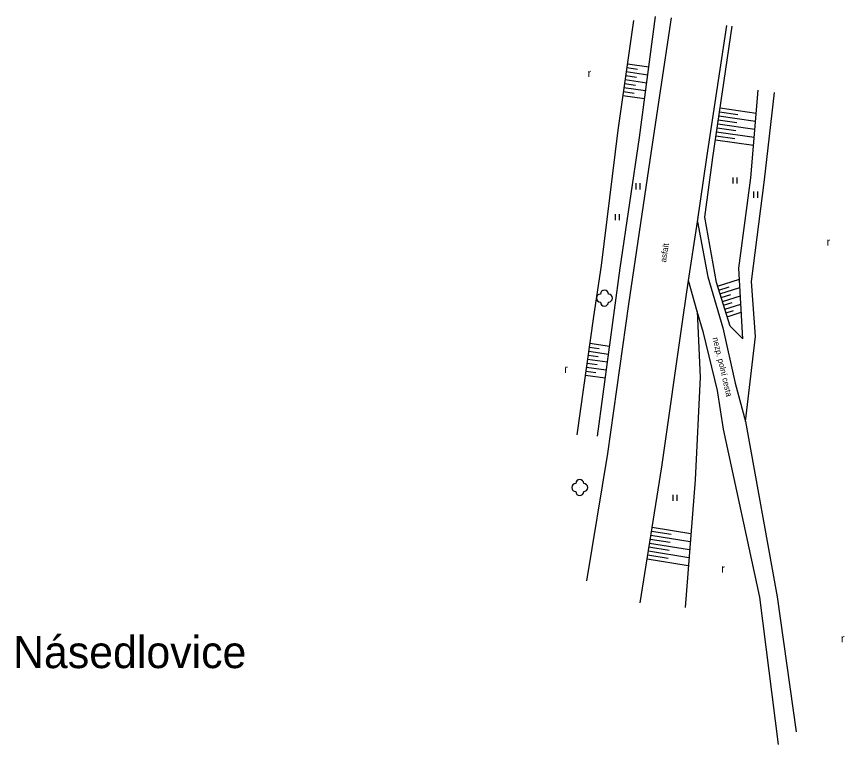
# Model space of a CAD drawing. Extents: x -582162 to -561283, y -1187583 to -1183539.
# Drawn here: x -575105.1 to -575001.7, y -1184397 to -1184306.2 of the extents above; entities that cross this region are included whole.
import ezdxf

# ---------------------------------------------------------------- set-up
doc = ezdxf.new("R2010")
doc.units = 0
for name, color, linetype in [('Vrstva 1', 7, 'Continuous'), ('Vrstva 10', 7, 'Continuous'), ('Vrstva 11', 7, 'Continuous'), ('Vrstva 12', 7, 'Continuous'), ('Vrstva 14', 7, 'Continuous'), ('Vrstva 17', 7, 'Continuous'), ('Vrstva 3', 7, 'Continuous')]:
    doc.layers.add(name, color=color, linetype=linetype)

# ---------------------------------------------------------------- blocks, each defined once
blk = doc.blocks.new('3.130')
at = {"layer": 'Vrstva 1'}
blk.add_circle((0, 0), 0.001, dxfattribs=at)
for centre, start, end in [((-1, 0), 90, 270), ((0, 1), 0, 180), ((1, 0), 270, 90), ((0, -1), 180, 360)]:
    blk.add_arc(centre, 1, start, end, dxfattribs=at)
blk = doc.blocks.new('3.019')
at = {"layer": 'Vrstva 1'}
blk.add_text('r', height=2, dxfattribs=at).set_placement((-0.496, -0.964))
blk = doc.blocks.new('3.060')
at = {"layer": 'Vrstva 1'}
for p, q in [((-0.5, -0.75), (-0.5, 0.75)), ((0.5, -0.75), (0.5, 0.75))]:
    blk.add_line(p, q, dxfattribs=at)

msp = doc.modelspace()

# ---------------------------------------------------------------- linework, layer by layer
at = {"layer": 'Vrstva 10'}
for points in [[(-575023.38, -1184306.34), (-575025.69, -1184321.89), (-575028.68, -1184342.1), (-575031.34, -1184360.73), (-575033.94, -1184376.61)], [(-575020.08, -1184331.81), (-575018.9, -1184323.77), (-575016.4, -1184307.33)], [(-575021.19, -1184339.11), (-575020.08, -1184331.81)], [(-575020.08, -1184331.81), (-575018.8, -1184338.69), (-575016.92, -1184345.02), (-575015.4, -1184351.95), (-575014.07, -1184356.71), (-575010.14, -1184378.61), (-575007.78, -1184395.44)], [(-575027.26, -1184379.33), (-575024.53, -1184362.37), (-575021.86, -1184343.7), (-575021.19, -1184339.11)], [(-575020.14, -1184342.98), (-575021.19, -1184339.11)], [(-575009.98, -1184397.01), (-575012.31, -1184378.63), (-575016.85, -1184357.66), (-575017.6, -1184352.85), (-575019.32, -1184345.64), (-575020.14, -1184342.98)]]:
    msp.add_lwpolyline(points, dxfattribs=at)
at = {"layer": 'Vrstva 11'}
msp.add_lwpolyline([(-575014.07, -1184356.71), (-575012.85, -1184346.12), (-575013.35, -1184339.27), (-575011.73, -1184326.56), (-575010.46, -1184315.68)], dxfattribs=at)
at = {"layer": 'Vrstva 12'}
for points in [[(-575028.06, -1184306.68), (-575030.03, -1184320.36), (-575032.1, -1184337.26), (-575033.05, -1184343.61), (-575035.13, -1184358.39)], [(-575032.59, -1184358.55), (-575029.74, -1184337.6), (-575027.34, -1184321.29), (-575025.33, -1184306.2)], [(-575014.44, -1184346.39), (-575016, -1184344.83), (-575017.73, -1184339.37), (-575019.16, -1184331.23), (-575018.18, -1184323.79), (-575015.77, -1184307.41)], [(-575028.84, -1184312.08), (-575026.16, -1184312.46)], [(-575028.98, -1184313.07), (-575026.3, -1184313.45)], [(-575028.91, -1184312.57), (-575027.57, -1184312.76)], [(-575029.12, -1184314.06), (-575026.43, -1184314.45)], [(-575029.05, -1184313.56), (-575027.71, -1184313.76)], [(-575029.27, -1184315.05), (-575026.56, -1184315.44)], [(-575029.19, -1184314.55), (-575027.84, -1184314.75)], [(-575029.41, -1184316.04), (-575026.69, -1184316.43)], [(-575029.34, -1184315.54), (-575027.98, -1184315.74)], [(-575014.44, -1184346.39), (-575014.91, -1184337.61), (-575013.42, -1184326.31), (-575012.5, -1184315.4)], [(-575017.34, -1184318.09), (-575015.06, -1184318.43)], [(-575017.27, -1184317.6), (-575012.74, -1184318.27)], [(-575017.49, -1184319.08), (-575015.18, -1184319.42)], [(-575017.42, -1184318.59), (-575012.83, -1184319.26)], [(-575017.63, -1184320.07), (-575015.29, -1184320.42)], [(-575017.56, -1184319.58), (-575012.91, -1184320.26)], [(-575017.85, -1184321.56), (-575013.08, -1184322.26)], [(-575017.78, -1184321.06), (-575015.41, -1184321.41)], [(-575017.71, -1184320.57), (-575012.99, -1184321.26)], [(-575017.58, -1184339.84), (-575014.84, -1184338.97)], [(-575017.43, -1184340.32), (-575016.12, -1184339.9)], [(-575017.28, -1184340.79), (-575014.78, -1184340)], [(-575017.13, -1184341.27), (-575015.94, -1184340.89)], [(-575016.98, -1184341.75), (-575014.73, -1184341.03)], [(-575016.83, -1184342.22), (-575015.76, -1184341.89)], [(-575016.68, -1184342.7), (-575014.67, -1184342.07)], [(-575020.14, -1184342.98), (-575019.76, -1184351.19), (-575020.38, -1184364), (-575021.64, -1184379.92)], [(-575016.52, -1184343.18), (-575015.58, -1184342.88)], [(-575016.37, -1184343.65), (-575014.62, -1184343.1)], [(-575033.52, -1184346.96), (-575031.06, -1184347.31)], [(-575033.73, -1184348.45), (-575032.5, -1184348.62)], [(-575033.66, -1184347.95), (-575031.19, -1184348.3)], [(-575033.59, -1184347.46), (-575032.36, -1184347.63)], [(-575033.87, -1184349.44), (-575032.63, -1184349.61)], [(-575033.8, -1184348.94), (-575031.33, -1184349.29)], [(-575034.01, -1184350.43), (-575032.77, -1184350.6)], [(-575033.94, -1184349.93), (-575031.47, -1184350.28)], [(-575034.08, -1184350.92), (-575031.6, -1184351.27)], [(-575025.74, -1184369.9), (-575020.91, -1184370.68)], [(-575025.9, -1184370.89), (-575020.99, -1184371.68)], [(-575025.82, -1184370.4), (-575023.39, -1184370.79)], [(-575026.06, -1184371.88), (-575021.07, -1184372.68)], [(-575025.98, -1184371.39), (-575023.5, -1184371.78)], [(-575026.22, -1184372.87), (-575021.15, -1184373.68)], [(-575026.14, -1184372.37), (-575023.62, -1184372.78)], [(-575026.38, -1184373.85), (-575021.23, -1184374.68)], [(-575026.3, -1184373.36), (-575023.74, -1184373.77)]]:
    msp.add_lwpolyline(points, dxfattribs=at)

# ---------------------------------------------------------------- block references
at = {"layer": 'Vrstva 11', "xscale": 0.5, "yscale": 0.5}
for p in [(-575031.7, -1184341.33), (-575034.79, -1184364.96)]:
    msp.add_blockref('3.130', p, dxfattribs=at)
at = {"layer": 'Vrstva 3', "xscale": 0.5, "yscale": 0.5}
for name, p in [('3.019', (-575033.54, -1184313.26)), ('3.060', (-575015.36, -1184326.66)), ('3.060', (-575027.48, -1184327.38)), ('3.060', (-575012.79, -1184328.42)), ('3.060', (-575030.07, -1184331.23)), ('3.019', (-575003.71, -1184334.32)), ('3.019', (-575036.48, -1184350.17)), ('3.060', (-575022.87, -1184366.26)), ('3.019', (-575016.87, -1184375.09)), ('3.019', (-575001.91, -1184383.79))]:
    msp.add_blockref(name, p, dxfattribs=at)

# ---------------------------------------------------------------- texts
at = {"layer": 'Vrstva 14'}
for s, rotation, p in [('asfalt', 81.354, (-575024.01, -1184336.91)), ('nezp. polní cesta', 283.418, (-575018.21, -1184346.31))]:
    msp.add_text(s, height=0.75, rotation=rotation, dxfattribs=at).set_placement(p)
at = {"layer": 'Vrstva 17'}
msp.add_text('Násedlovice', height=4, dxfattribs=at).set_placement((-575105.55, -1184387.49))

doc.saveas('drawing.dxf')
